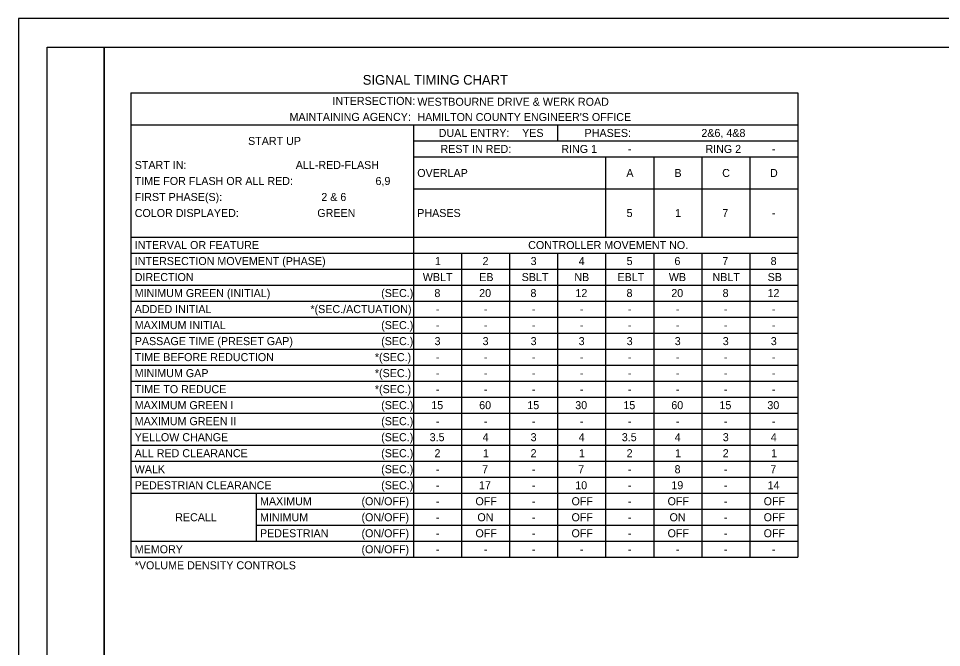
# Model space of a CAD drawing. Extents: x 5.5 to 39.5, y -2.1 to 19.9.
# Drawn here: x 5.55 to 21.69, y 8.91 to 19.91 of the extents above; entities that cross this region are included whole.
import ezdxf

# ---------------------------------------------------------------- set-up
doc = ezdxf.new("R2010")
doc.units = 0
for name, color, linetype in [('Default', 7, 'Continuous'), ('DR_X_Cells', 7, 'Continuous'), ('SC_Scratch1', 7, 'Continuous'), ('UT_X_Misc_Cells', 7, 'Continuous')]:
    doc.layers.add(name, color=color, linetype=linetype)

msp = doc.modelspace()

# ---------------------------------------------------------------- linework, layer by layer
at = {"layer": 'Default'}
for p, q in [((7.515, 18.61), (19.177, 18.61)), ((7.515, 18.61), (7.515, 10.49)), ((19.177, 18.61), (19.177, 10.49)), ((7.515, 18.05), (19.177, 18.05)), ((12.457, 18.05), (12.457, 10.49)), ((14.977, 18.05), (14.977, 17.77)), ((12.457, 17.77), (19.177, 17.77)), ((12.457, 17.49), (19.177, 17.49)), ((15.817, 17.49), (15.817, 16.09)), ((16.657, 17.49), (16.657, 16.09)), ((17.497, 17.49), (17.497, 16.09)), ((18.337, 17.49), (18.337, 16.09)), ((12.457, 16.93), (19.177, 16.93)), ((7.515, 16.09), (19.177, 16.09)), ((7.515, 15.81), (19.177, 15.81)), ((13.297, 15.81), (13.297, 10.49)), ((14.137, 15.81), (14.137, 10.49)), ((14.977, 15.81), (14.977, 10.49)), ((15.817, 15.81), (15.817, 10.49)), ((16.657, 15.81), (16.657, 10.49)), ((17.497, 15.81), (17.497, 10.49)), ((18.337, 15.81), (18.337, 10.49)), ((7.515, 15.53), (19.177, 15.53)), ((7.515, 15.25), (19.177, 15.25)), ((7.515, 14.97), (19.177, 14.97)), ((7.515, 14.69), (19.177, 14.69)), ((7.515, 14.41), (19.177, 14.41)), ((7.515, 14.13), (19.177, 14.13)), ((7.515, 13.85), (19.177, 13.85)), ((7.515, 13.57), (19.177, 13.57)), ((7.515, 13.29), (19.177, 13.29)), ((7.515, 13.01), (19.177, 13.01)), ((7.515, 12.73), (19.177, 12.73)), ((7.515, 12.45), (19.177, 12.45)), ((7.515, 12.17), (19.177, 12.17)), ((7.515, 11.89), (19.177, 11.89)), ((7.515, 11.61), (19.177, 11.61)), ((9.706, 11.61), (9.706, 10.77)), ((9.706, 11.33), (19.177, 11.33)), ((9.706, 11.05), (19.177, 11.05)), ((7.515, 10.77), (19.177, 10.77)), ((7.515, 10.49), (19.177, 10.49))]:
    msp.add_line(p, q, dxfattribs=at)
at = {"layer": 'DR_X_Cells'}
msp.add_lwpolyline([(5.548, -2.088), (39.548, -2.088), (39.548, 19.912), (5.548, 19.912)], close=True, dxfattribs=at)
at = {"layer": 'SC_Scratch1'}
for points in [[(6.048, 19.412), (7.048, 19.412), (7.048, -1.588), (6.048, -1.588)], [(7.048, 19.412), (39.048, 19.412), (39.048, -1.588), (7.048, -1.588)]]:
    msp.add_lwpolyline(points, close=True, dxfattribs=at)

# ---------------------------------------------------------------- texts
at = {"layer": 'Default'}
for s, p in [('INTERSECTION:', (11.04, 18.4)), ('WESTBOURNE DRIVE & WERK ROAD', (12.524, 18.385)), ('MAINTAINING AGENCY:', (10.288, 18.12)), ("HAMILTON COUNTY ENGINEER'S OFFICE", (12.524, 18.118)), ('DUAL ENTRY: ', (12.897, 17.84)), ('YES', (14.356, 17.84)), ('PHASES:', (15.449, 17.84)), ('2&6, 4&8', (17.491, 17.84)), ('START UP', (9.563, 17.7)), ('REST IN RED: ', (12.928, 17.56)), ('RING 1', (15.042, 17.56)), ('-', (16.206, 17.56)), ('RING 2', (17.562, 17.56)), ('-', (18.726, 17.56)), ('START IN: ', (7.581, 17.28)), ('ALL-RED-FLASH', (10.397, 17.28)), ('OVERLAP', (12.522, 17.14)), ('A', (16.179, 17.14)), ('B', (17.02, 17.14)), ('C', (17.855, 17.14)), ('D', (18.691, 17.14)), ('TIME FOR FLASH OR ALL RED:   ', (7.581, 17)), ('6,9', (11.792, 17)), ('FIRST PHASE(S):', (7.581, 16.72)), ('2 & 6', (10.844, 16.72)), ('COLOR DISPLAYED:', (7.581, 16.44)), ('GREEN', (10.774, 16.44)), ('PHASES', (12.522, 16.44)), ('5', (16.183, 16.44)), ('1', (17.031, 16.44)), ('7', (17.857, 16.44)), ('-', (18.726, 16.44)), ('INTERVAL OR FEATURE', (7.581, 15.88)), ('CONTROLLER MOVEMENT NO.', (14.462, 15.88)), ('INTERSECTION MOVEMENT (PHASE)', (7.581, 15.6)), ('1', (12.831, 15.6)), ('2', (13.664, 15.6)), ('3', (14.505, 15.6)), ('4', (15.345, 15.6)), ('5', (16.183, 15.6)), ('6', (17.02, 15.6)), ('7', (17.857, 15.6)), ('8', (18.702, 15.6)), ('DIRECTION', (7.581, 15.32)), ('WBLT', (12.619, 15.32)), ('EB', (13.606, 15.32)), ('SBLT', (14.348, 15.32)), ('NB', (15.269, 15.32)), ('EBLT', (16.024, 15.32)), ('WB', (16.922, 15.32)), ('NBLT', (17.686, 15.32)), ('SB', (18.65, 15.32)), ('MINIMUM GREEN (INITIAL) ', (7.581, 15.04)), ('(SEC.)', (11.891, 15.04)), ('8', (12.822, 15.04)), ('20', (13.605, 15.04)), ('8', (14.502, 15.04)), ('12', (15.288, 15.04)), ('8', (16.182, 15.04)), ('20', (16.965, 15.04)), ('8', (17.862, 15.04)), ('12', (18.648, 15.04)), ('ADDED INITIAL', (7.581, 14.76)), ('*(SEC./ACTUATION)', (10.654, 14.76)), ('-', (12.846, 14.76)), ('-', (13.686, 14.76)), ('-', (14.526, 14.76)), ('-', (15.366, 14.76)), ('-', (16.206, 14.76)), ('-', (17.046, 14.76)), ('-', (17.886, 14.76)), ('-', (18.726, 14.76)), ('MAXIMUM INITIAL', (7.581, 14.48)), ('(SEC.)', (11.891, 14.48)), ('-', (12.846, 14.48)), ('-', (13.686, 14.48)), ('-', (14.526, 14.48)), ('-', (15.366, 14.48)), ('-', (16.206, 14.48)), ('-', (17.046, 14.48)), ('-', (17.886, 14.48)), ('-', (18.726, 14.48)), ('PASSAGE TIME (PRESET GAP)', (7.581, 14.2)), ('(SEC.)', (11.891, 14.2)), ('3', (12.825, 14.2)), ('3', (13.665, 14.2)), ('3', (14.505, 14.2)), ('3', (15.345, 14.2)), ('3', (16.185, 14.2)), ('3', (17.025, 14.2)), ('3', (17.865, 14.2)), ('3', (18.705, 14.2)), ('TIME BEFORE REDUCTION', (7.581, 13.92)), ('*(SEC.)', (11.781, 13.92)), ('-', (12.846, 13.92)), ('-', (13.686, 13.92)), ('-', (14.526, 13.92)), ('-', (15.366, 13.92)), ('-', (16.206, 13.92)), ('-', (17.046, 13.92)), ('-', (17.886, 13.92)), ('-', (18.726, 13.92)), ('MINIMUM GAP', (7.581, 13.64)), ('*(SEC.)', (11.781, 13.64)), ('-', (12.846, 13.64)), ('-', (13.686, 13.64)), ('-', (14.526, 13.64)), ('-', (15.366, 13.64)), ('-', (16.206, 13.64)), ('-', (17.046, 13.64)), ('-', (17.886, 13.64)), ('-', (18.726, 13.64)), ('TIME TO REDUCE', (7.581, 13.36)), ('*(SEC.)', (11.781, 13.36)), ('-', (12.846, 13.36)), ('-', (13.686, 13.36)), ('-', (14.526, 13.36)), ('-', (15.366, 13.36)), ('-', (16.206, 13.36)), ('-', (17.046, 13.36)), ('-', (17.886, 13.36)), ('-', (18.726, 13.36)), ('MAXIMUM GREEN I', (7.581, 13.08)), ('(SEC.)', (11.891, 13.08)), ('15', (12.767, 13.08)), ('60', (13.605, 13.08)), ('15', (14.447, 13.08)), ('30', (15.285, 13.08)), ('15', (16.127, 13.08)), ('60', (16.965, 13.08)), ('15', (17.807, 13.08)), ('30', (18.645, 13.08)), ('MAXIMUM GREEN II', (7.581, 12.8)), ('(SEC.)', (11.891, 12.8)), ('-', (12.846, 12.8)), ('-', (13.686, 12.8)), ('-', (14.526, 12.8)), ('-', (15.366, 12.8)), ('-', (16.206, 12.8)), ('-', (17.046, 12.8)), ('-', (17.886, 12.8)), ('-', (18.726, 12.8)), ('YELLOW CHANGE', (7.581, 12.52)), ('(SEC.)', (11.891, 12.52)), ('3.5', (12.739, 12.52)), ('4', (13.665, 12.52)), ('3', (14.505, 12.52)), ('4', (15.345, 12.52)), ('3.5', (16.099, 12.52)), ('4', (17.025, 12.52)), ('3', (17.865, 12.52)), ('4', (18.705, 12.52)), ('ALL RED CLEARANCE', (7.581, 12.24)), ('(SEC.)', (11.891, 12.24)), ('2', (12.824, 12.24)), ('1', (13.671, 12.24)), ('2', (14.504, 12.24)), ('1', (15.351, 12.24)), ('2', (16.184, 12.24)), ('1', (17.031, 12.24)), ('2', (17.864, 12.24)), ('1', (18.711, 12.24)), ('WALK', (7.581, 11.96)), ('(SEC.)', (11.891, 11.96)), ('-', (12.846, 11.96)), ('7', (13.657, 11.96)), ('-', (14.526, 11.96)), ('7', (15.337, 11.96)), ('-', (16.206, 11.96)), ('8', (17.022, 11.96)), ('-', (17.886, 11.96)), ('7', (18.697, 11.96)), ('PEDESTRIAN CLEARANCE', (7.581, 11.68)), ('(SEC.)', (11.891, 11.68)), ('17', (13.602, 11.68)), ('10', (15.285, 11.68)), ('19', (16.966, 11.68)), ('14', (18.649, 11.68)), ('-', (12.846, 11.68)), ('-', (14.526, 11.68)), ('-', (16.206, 11.68)), ('-', (17.886, 11.68)), ('MAXIMUM', (9.772, 11.4)), ('(ON/OFF)', (11.547, 11.4)), ('-', (12.846, 11.4)), ('OFF', (13.54, 11.4)), ('-', (14.526, 11.4)), ('OFF', (15.22, 11.4)), ('-', (16.206, 11.4)), ('OFF', (16.9, 11.4)), ('-', (17.886, 11.4)), ('OFF', (18.58, 11.4)), ('RECALL', (8.289, 11.12)), ('MINIMUM', (9.772, 11.12)), ('(ON/OFF)', (11.547, 11.12)), ('-', (12.846, 11.12)), ('ON', (13.574, 11.12)), ('-', (14.526, 11.12)), ('OFF', (15.22, 11.12)), ('-', (16.206, 11.12)), ('ON', (16.934, 11.12)), ('-', (17.886, 11.12)), ('OFF', (18.58, 11.12)), ('PEDESTRIAN', (9.772, 10.84)), ('(ON/OFF)', (11.547, 10.84)), ('OFF', (13.54, 10.84)), ('OFF', (15.22, 10.84)), ('OFF', (16.9, 10.84)), ('OFF', (18.58, 10.84)), ('-', (12.846, 10.84)), ('-', (14.526, 10.84)), ('-', (16.206, 10.84)), ('-', (17.886, 10.84)), ('MEMORY    ', (7.581, 10.56)), ('(ON/OFF)', (11.547, 10.56)), ('-', (12.846, 10.56)), ('-', (13.686, 10.56)), ('-', (14.526, 10.56)), ('-', (15.366, 10.56)), ('-', (16.206, 10.56)), ('-', (17.046, 10.56)), ('-', (17.886, 10.56)), ('-', (18.726, 10.56)), ('*VOLUME DENSITY CONTROLS', (7.581, 10.28))]:
    msp.add_text(s, height=0.14, dxfattribs=at).set_placement(p)
at = {"layer": 'UT_X_Misc_Cells'}
msp.add_text('SIGNAL TIMING CHART ', height=0.17, dxfattribs=at).set_placement((11.569, 18.753))

doc.saveas('drawing.dxf')
